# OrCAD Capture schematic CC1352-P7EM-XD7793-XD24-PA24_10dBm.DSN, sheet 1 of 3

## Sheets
1 Mechanical: size A3; title: CC1352-P7EM-XD7793-XD24-PA24_10dBm; rev: B0
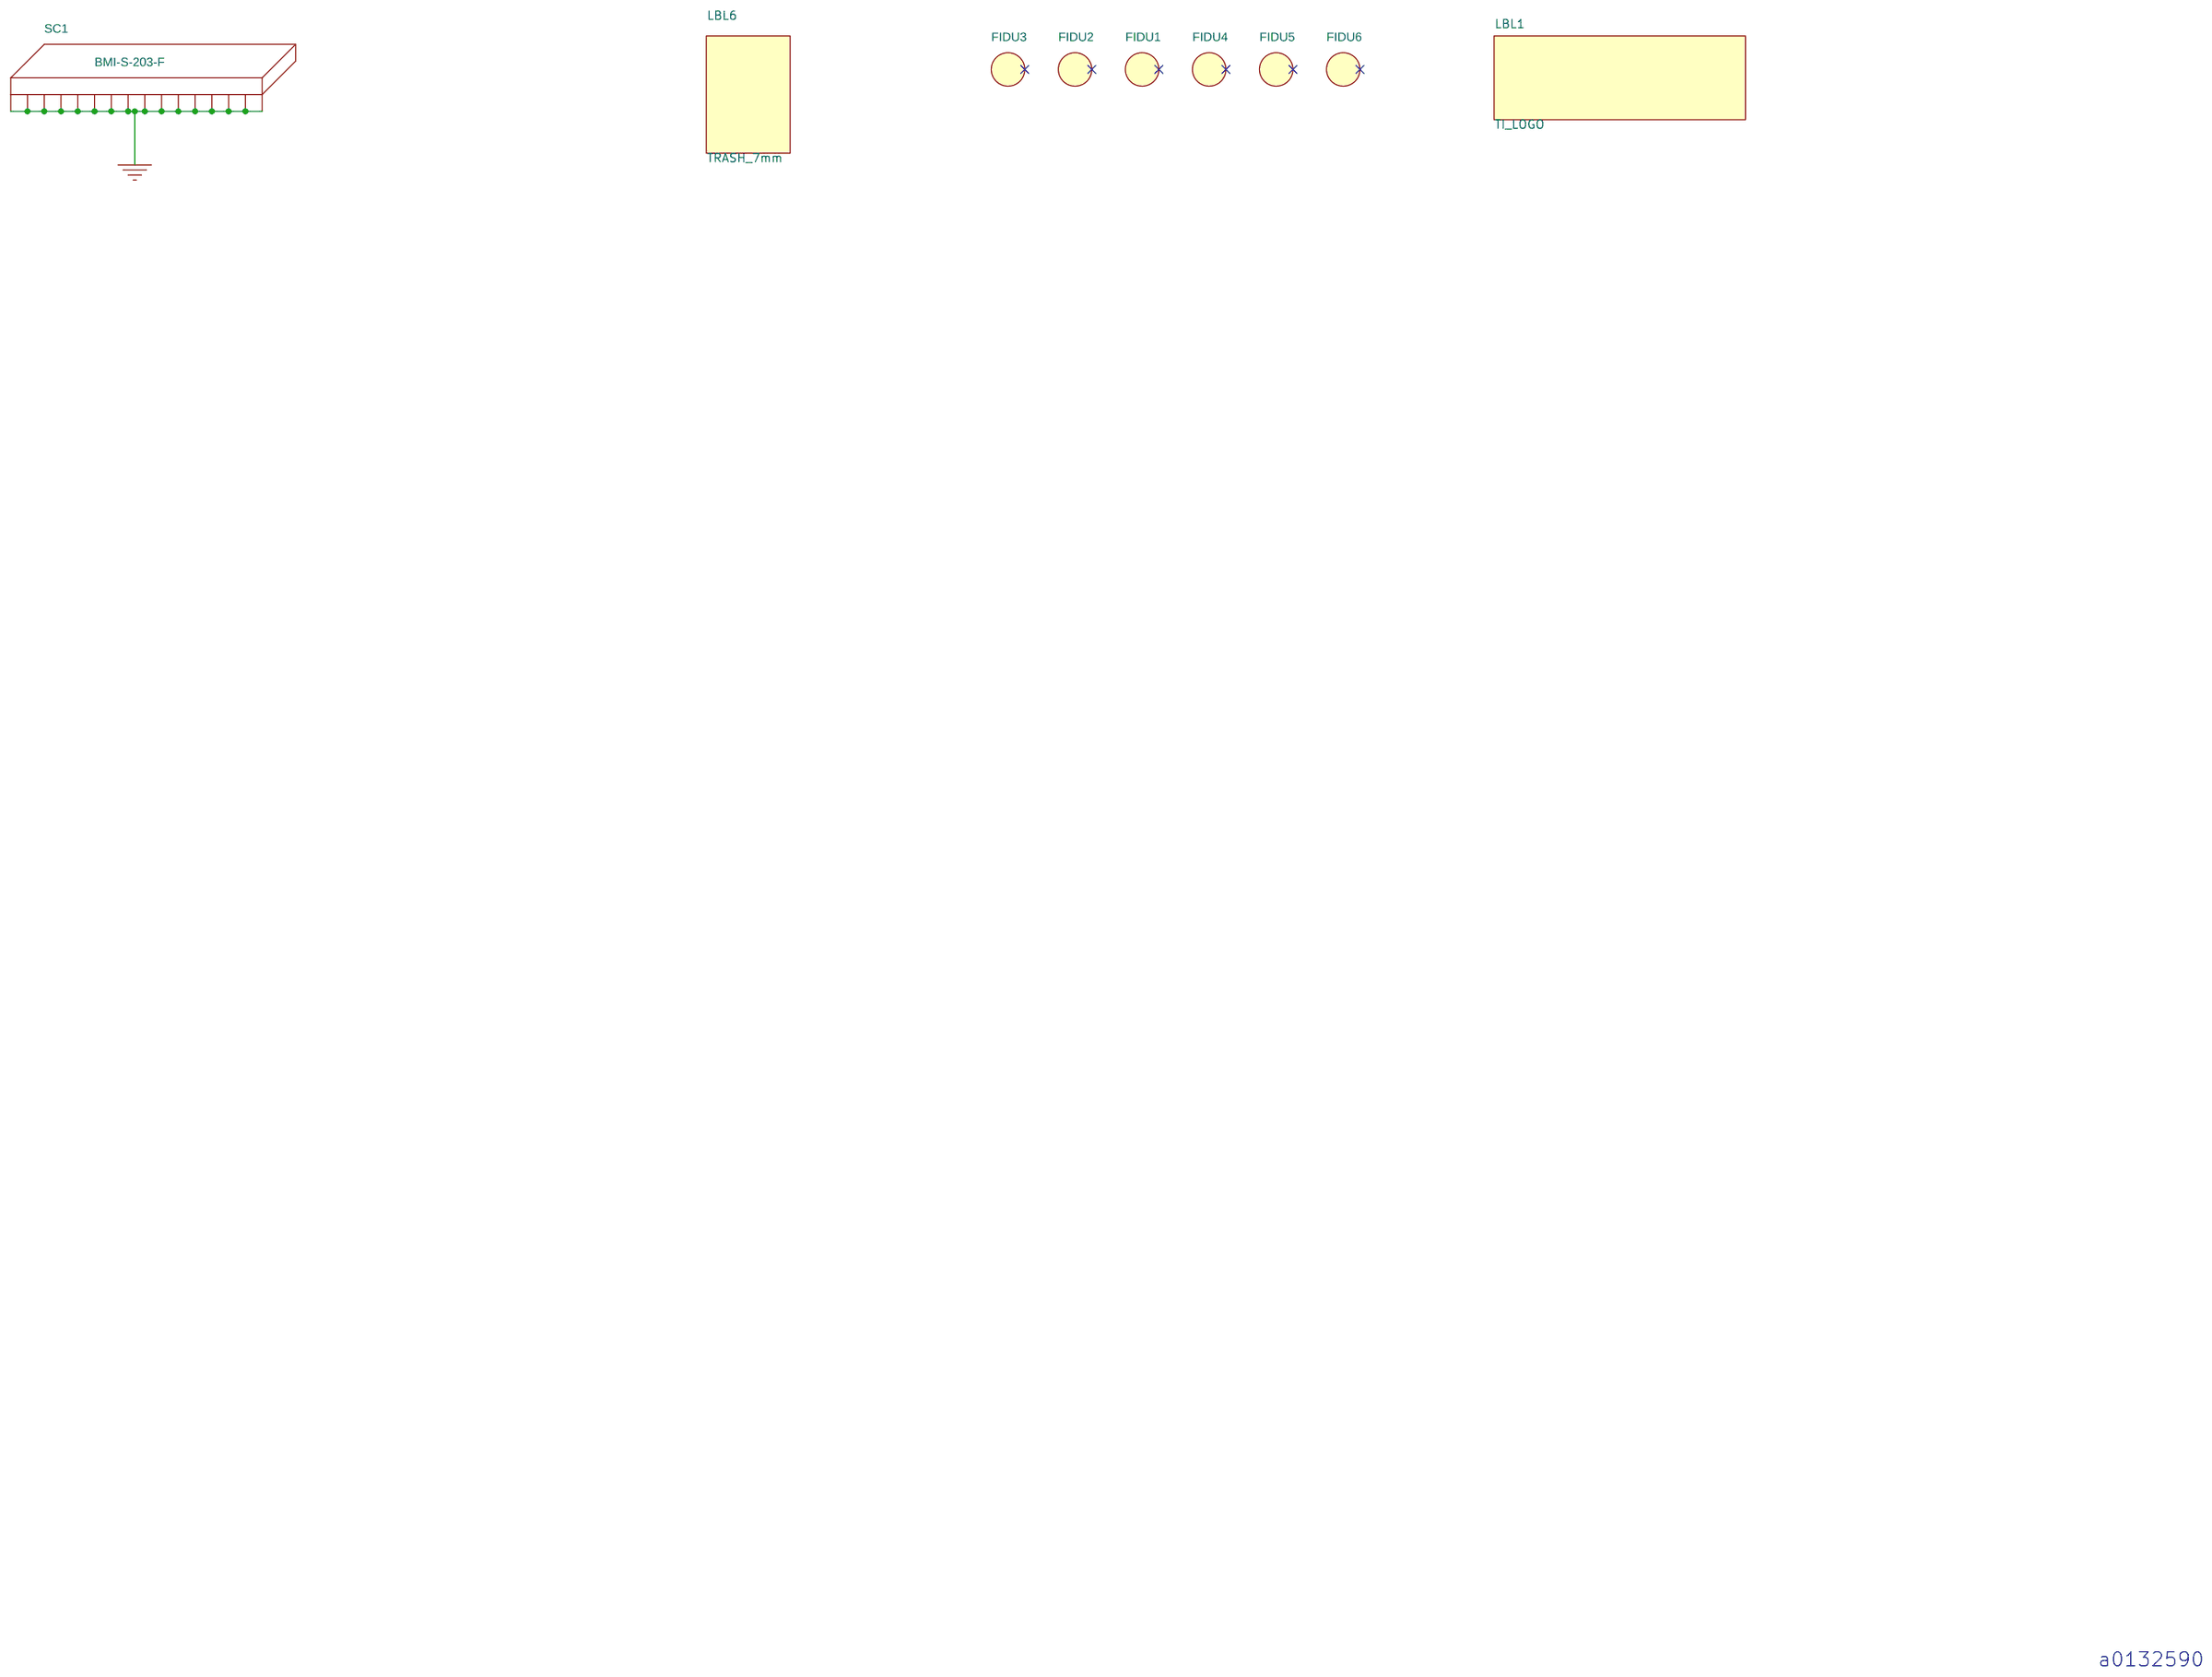
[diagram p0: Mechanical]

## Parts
FIDU1  FIDU_1MM  [FID100X115B]
FIDU2  FIDU_1MM  [FID100X115B]
FIDU3  FIDU_1MM  [FID100X115B]
FIDU4  FIDU_1MM  [FID100X115B]
FIDU5  FIDU_1MM  [FID100X115B]
FIDU6  FIDU_1MM  [FID100X115B]
LBL1  TI_LOGO  [TI_LOGO_1]
LBL6  TRASH_7mm  [TRASH_7MM]
SC1  BMI-S-203-F  [MECH_BMIS203_A2N]

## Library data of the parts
FIDU1-FIDU6 = FIDMARK: NON COMPONENT, FIDUCIAL MARK, ROUND 1mm, SMD; Additional Datasheet URL: N/A; AutoDoc File: https://notefied-dynamic-precision.com/DB/Apps/Desktop/Item/Object.aspx?id=74548; BU Name: DYNAMIC PRECISION GDANSK; CLASS: IO; Country of Origin: Missing Info; Datasheet URL: N/A; Mass: N/A; Mounting Type: SMD; NOTEfied URL: https://notefied-dynamic-precision.com/NOTEfiedWebInterface/part/show?partNumber=19-00111; Old Footprint: FID100X115; Packing Size: N/A; Packing Type: Missing Info; Part Number: 19-00111; Part Type: Non Component|FIDUCIAL; ROHS: Compliant; Revision: R022; Status: Released; Type: Non Component; Vendor: NON_COMPONENT; Vendor Part Number: FIDUCIAL_1mm; Vendor Part Status: Active
LBL1 = TI_LOGO_V1: NON COMPONENT, LABEL, TEXAS INSTRUMENTS LOGO; Additional Datasheet URL: N/A; AutoDoc File: https://notefied-dynamic-precision.com/DB/Apps/Desktop/Item/Object.aspx?id=87770; BU Name: TEXAS INSTRUMENTS NORWAY; Country of Origin: Missing Info; Datasheet URL: N/A; Exclusive for Customers: TEXAS INSTRUMENTS NORWAY; Mass: N/A; Mounting Type: NOT APPLY; NOTEfied URL: https://notefied-dynamic-precision.com/NOTEfiedWebInterface/part/show?partNumber=19-00350; Notes: Custom Item; Packing Size: N/A; Packing Type: Missing Info; Part Number: 19-00350; Part Type: Non Component|LABEL; ROHS: Missing Info; Revision: R018; Status: Released; Texas Part Status: Under Review; Type: Non Component; Vendor: NON_COMPONENT; Vendor Part Status: Active
LBL6 = TRASH_V2: NON COMPONENT, LABEL, TRASH 7mm; Additional Datasheet URL: N/A; Country of Origin: Missing Info; Datasheet URL: N/A; Mass: N/A; Mounting Type: NOT APPLY; NOTEfied URL: https://notefied-dynamic-precision.com/NOTEfiedWebInterface/part/show?partNumber=19-01044; Packing Size: N/A; Packing Type: Missing Info; Part Number: 19-01044; Part Type: Non Component|LABEL; ROHS: Missing Info; Revision: R012; Status: Released; Texas Part Status: Under Review; Type: Non Component; Vendor: NON_COMPONENT; Vendor Part Status: Active
SC1 = SHIELD_COVER_BMIS-203: MECHANIC, FRAME FOR SHIELD BMI-S-203, SMD; Additional Datasheet URL: https://www.laird.com/sites/default/files/2018-11/EMI-CAT-Essentials%201213.pdf; AutoDoc File: https://notefied-dynamic-precision.com/DB/Apps/Desktop/Item/Object.aspx?id=57168; BU Name: DYNAMIC PRECISION GDANSK; Budget Currency: EUR; Budget Price: 1.11; Budgetary Price: 1.37655 USD; CLASS: IC; Client Status: UNDER_REVIEW; Country of Origin: Czech Republic; Datasheet URL: https://www.laird.com/sites/default/files/2018-11/Board%20Level%20Shields%20Catalog%20Download.pdf; Datasheet URL 1: http://cdn.lairdtech.com/home/brandworld/files/Board%20Level%20Shields%20Catalog%20Download.pdf; Datasheet URL 2: http://cdn.lairdtech.com/home/brandworld/files/EMI-CAT-Essentials%201213.pdf; Lead Time: 4; Mass: 1g; Max Oper Temp: +85DEGC; Maximum Operating Temperature: +85DEGC; Min Oper Temp: -40DEGC; Minimum Operating Temperature: -40DEGC; Mounting Type: SMD; NOTEfied URL: https://notefied-dynamic-precision.com/NOTEfiedWebInterface/part/show?partNumber=13-00133; Packing Size: 300; Packing Type: Tape & Reel; Part Number: 13-00133; Part Type: Mechanic|SHIELD; REACH/SVHC Compliance: Compliant; REACH/SVHC Details: SVHC List Version Jan 15, 2018; REACH/SVHC Source: REACH Declaration; REACH/SVHC Status: Unaffected; ROHS: Compliant; Revision: R023; RoHS Status: ROHS_COMPLIANT; Status: Released; Texas Part Status: Under Review; Type: Mechanic; Vendor: LAIRD; Vendor Part Status: Active; Weight: 1g

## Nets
GND: SC1.1(GND) SC1.2(GND) SC1.3(GND) SC1.4(GND) SC1.5(GND) SC1.6(GND) SC1.7(GND) SC1.8(GND) SC1.9(GND) SC1.10(GND) SC1.11(GND) SC1.12(GND) SC1.13(GND) SC1.14(GND) SC1.15(GND) SC1.16(GND) ; also on sheet 2

Not connected (* = marked no-connect by the designer): FIDU1 1*; FIDU2 1*; FIDU3 1*; FIDU4 1*; FIDU5 1*; FIDU6 1*

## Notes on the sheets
sheet 1
- a0132590
